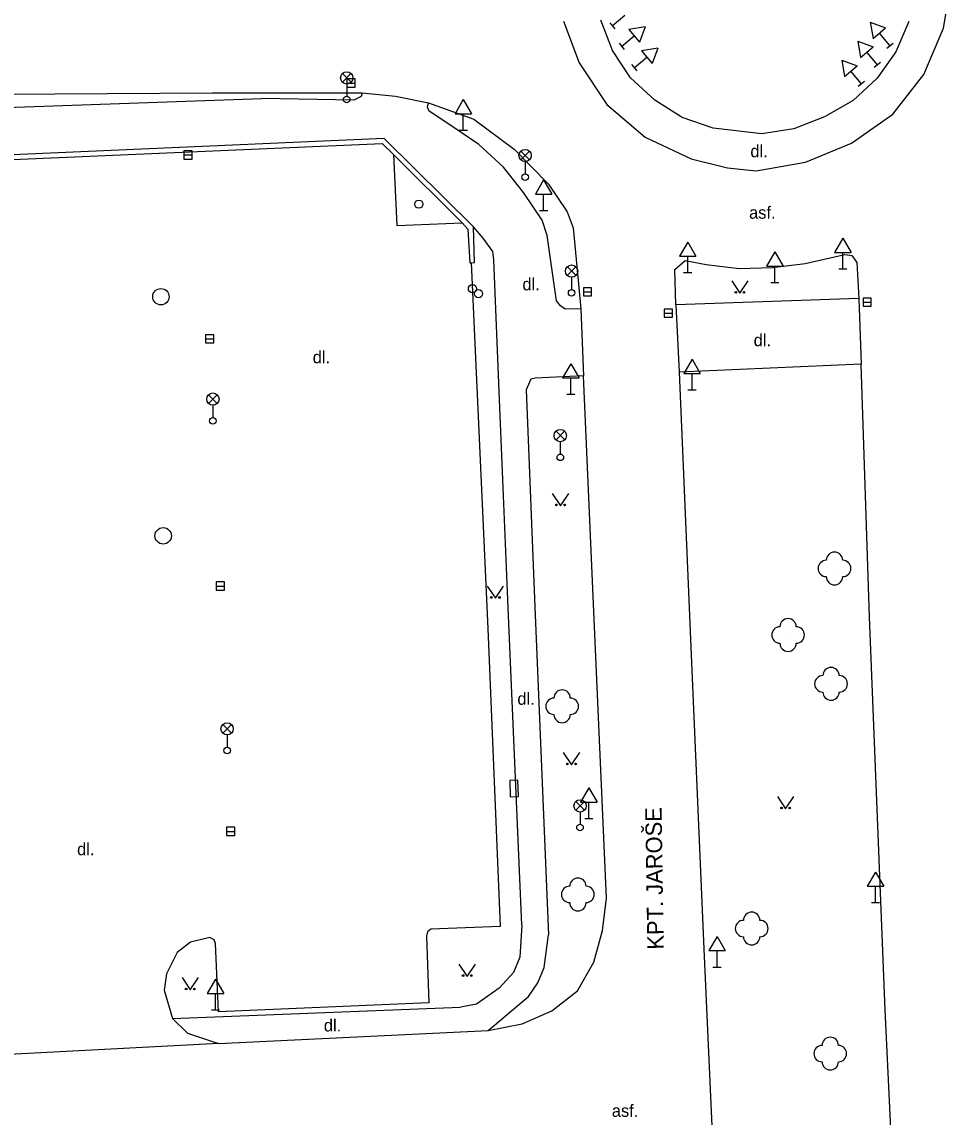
# Model space of a CAD drawing. Extents: x -737812 to -729375, y -1123000 to -1115500.
# Drawn here: x -736401.9 to -736345.8, y -1118917.3 to -1118850.5 of the extents above; entities that cross this region are included whole.
import ezdxf

# ---------------------------------------------------------------- set-up
doc = ezdxf.new("R2010")
doc.units = 0
for name, color, linetype in [('Doplněk polohopisu', 7, 'Continuous'), ('Doplňkové značky', 7, 'Continuous'), ('Hranice - ploty_ zdi', 7, 'Continuous'), ('Komunikace', 7, 'Continuous'), ('Názvy ulic_ silnic_ žel_', 7, 'Continuous'), ('Pomocné popisy', 7, 'Continuous'), ('Povr_ zn_ inž_ sítí - el_', 7, 'Continuous'), ('Povr_ zn_ inž_ sítí - kan_', 7, 'Continuous'), ('Povr_ zn_ inž_ sítí - vod_', 7, 'Continuous'), ('Zeleň', 7, 'Continuous'), ('Značky druhů pozemků', 7, 'Continuous')]:
    doc.layers.add(name, color=color, linetype=linetype)

msp = doc.modelspace()

# ---------------------------------------------------------------- linework, layer by layer
at = {"layer": 'Doplněk polohopisu'}
for points in [[(-736453.53, -1118857.19), (-736433.11, -1118856.6), (-736413.31, -1118856.09), (-736387.26, -1118855.18)], [(-736381.14, -1118854.83), (-736381.2, -1118855.06), (-736381.66, -1118855.27), (-736387.26, -1118855.18)], [(-736367.8, -1118868), (-736368.76, -1118868.02), (-736369.05, -1118867.83), (-736369.3, -1118867.52), (-736369.87, -1118863.53), (-736370.17, -1118862.59), (-736371.3, -1118860.9), (-736372.53, -1118859.36), (-736374.02, -1118857.98), (-736375.67, -1118856.86), (-736377.05, -1118855.95), (-736377.16, -1118855.7), (-736377.1, -1118855.44)], [(-736371.4, -1118905.59), (-736372.21, -1118887.2), (-736372.78, -1118873.05), (-736373.12, -1118865.01), (-736373.17, -1118864.51), (-736373.76, -1118863.69), (-736374.36, -1118863)], [(-736350.85, -1118867.38), (-736362.01, -1118867.76)], [(-736350.72, -1118871.39), (-736361.81, -1118871.88)], [(-736367.64, -1118872.1), (-736370.6, -1118872.23), (-736370.85, -1118872.29), (-736371.14, -1118872.95), (-736370.6, -1118886.7), (-736369.78, -1118906.21)], [(-736371.4, -1118905.59), (-736371.53, -1118907.57), (-736371.91, -1118908.5), (-736372.78, -1118909.46), (-736374.17, -1118910.44), (-736375.15, -1118910.62)], [(-736373.47, -1118912.04), (-736371.01, -1118909.97), (-736370.44, -1118909.13), (-736370.05, -1118908.2), (-736369.78, -1118906.21)], [(-736392.71, -1118911.31), (-736375.15, -1118910.62)]]:
    msp.add_lwpolyline(points, dxfattribs=at)
at = {"layer": 'Doplňkové značky'}
for p, q in [((-736366.051, -1118850.548), (-736365.729, -1118850.932)), ((-736365.89, -1118850.74), (-736365.124, -1118850.097)), ((-736350.159, -1118850.521), (-736349.986, -1118851.505)), ((-736350.159, -1118850.521), (-736349.22, -1118850.863)), ((-736363.891, -1118850.801), (-736364.875, -1118850.974)), ((-736364.875, -1118850.974), (-736364.233, -1118851.74)), ((-736363.891, -1118850.801), (-736364.233, -1118851.74)), ((-736349.986, -1118851.505), (-736349.22, -1118850.863)), ((-736348.96, -1118851.95), (-736349.603, -1118851.184)), ((-736365.481, -1118851.808), (-736365.159, -1118852.192)), ((-736365.32, -1118852), (-736364.554, -1118851.357)), ((-736350.919, -1118851.681), (-736350.746, -1118852.665)), ((-736350.919, -1118851.681), (-736349.98, -1118852.023)), ((-736349.152, -1118852.111), (-736348.768, -1118851.789)), ((-736364.55, -1118853.3), (-736363.784, -1118852.657)), ((-736363.121, -1118852.101), (-736364.105, -1118852.274)), ((-736364.105, -1118852.274), (-736363.463, -1118853.04)), ((-736363.121, -1118852.101), (-736363.463, -1118853.04)), ((-736350.746, -1118852.665), (-736349.98, -1118852.023)), ((-736349.72, -1118853.11), (-736350.363, -1118852.344)), ((-736364.711, -1118853.108), (-736364.389, -1118853.492)), ((-736351.899, -1118852.841), (-736351.726, -1118853.825)), ((-736351.899, -1118852.841), (-736350.96, -1118853.183)), ((-736351.726, -1118853.825), (-736350.96, -1118853.183)), ((-736349.912, -1118853.271), (-736349.528, -1118852.949)), ((-736350.7, -1118854.27), (-736351.343, -1118853.504)), ((-736350.892, -1118854.431), (-736350.508, -1118854.109)), ((-736374.98, -1118855.244), (-736375.48, -1118856.11)), ((-736374.98, -1118855.244), (-736374.48, -1118856.11)), ((-736375.48, -1118856.11), (-736374.48, -1118856.11)), ((-736374.98, -1118857.11), (-736374.98, -1118856.11)), ((-736375.23, -1118857.11), (-736374.73, -1118857.11)), ((-736370.08, -1118860.144), (-736370.58, -1118861.01)), ((-736370.08, -1118860.144), (-736369.58, -1118861.01)), ((-736370.58, -1118861.01), (-736369.58, -1118861.01)), ((-736370.08, -1118862.01), (-736370.08, -1118861.01)), ((-736370.33, -1118862.01), (-736369.83, -1118862.01)), ((-736361.29, -1118863.934), (-736361.79, -1118864.8)), ((-736361.29, -1118863.934), (-736360.79, -1118864.8)), ((-736351.83, -1118863.704), (-736352.33, -1118864.57)), ((-736351.83, -1118863.704), (-736351.33, -1118864.57)), ((-736355.98, -1118864.534), (-736356.48, -1118865.4)), ((-736355.98, -1118864.534), (-736355.48, -1118865.4)), ((-736352.33, -1118864.57), (-736351.33, -1118864.57)), ((-736351.83, -1118865.57), (-736351.83, -1118864.57)), ((-736361.79, -1118864.8), (-736360.79, -1118864.8)), ((-736361.29, -1118865.8), (-736361.29, -1118864.8)), ((-736361.54, -1118865.8), (-736361.04, -1118865.8)), ((-736356.48, -1118865.4), (-736355.48, -1118865.4)), ((-736355.98, -1118866.4), (-736355.98, -1118865.4)), ((-736352.08, -1118865.57), (-736351.58, -1118865.57)), ((-736356.23, -1118866.4), (-736355.73, -1118866.4)), ((-736368.42, -1118871.354), (-736368.92, -1118872.22)), ((-736368.42, -1118871.354), (-736367.92, -1118872.22)), ((-736361.03, -1118871.084), (-736361.53, -1118871.95)), ((-736361.03, -1118871.084), (-736360.53, -1118871.95)), ((-736361.53, -1118871.95), (-736360.53, -1118871.95)), ((-736361.03, -1118872.95), (-736361.03, -1118871.95)), ((-736368.92, -1118872.22), (-736367.92, -1118872.22)), ((-736368.42, -1118873.22), (-736368.42, -1118872.22)), ((-736368.67, -1118873.22), (-736368.17, -1118873.22)), ((-736361.28, -1118872.95), (-736360.78, -1118872.95)), ((-736367.32, -1118897.244), (-736367.82, -1118898.11)), ((-736367.32, -1118897.244), (-736366.82, -1118898.11)), ((-736367.82, -1118898.11), (-736366.82, -1118898.11)), ((-736367.32, -1118899.11), (-736367.32, -1118898.11)), ((-736367.57, -1118899.11), (-736367.07, -1118899.11)), ((-736349.84, -1118902.374), (-736350.34, -1118903.24)), ((-736349.84, -1118902.374), (-736349.34, -1118903.24)), ((-736350.34, -1118903.24), (-736349.34, -1118903.24)), ((-736349.84, -1118904.24), (-736349.84, -1118903.24)), ((-736350.09, -1118904.24), (-736349.59, -1118904.24)), ((-736359.5, -1118906.304), (-736360, -1118907.17)), ((-736359.5, -1118906.304), (-736359, -1118907.17)), ((-736360, -1118907.17), (-736359, -1118907.17)), ((-736359.5, -1118908.17), (-736359.5, -1118907.17)), ((-736359.75, -1118908.17), (-736359.25, -1118908.17)), ((-736390.09, -1118908.914), (-736390.59, -1118909.78)), ((-736390.09, -1118908.914), (-736389.59, -1118909.78)), ((-736390.59, -1118909.78), (-736389.59, -1118909.78)), ((-736390.09, -1118910.78), (-736390.09, -1118909.78)), ((-736390.34, -1118910.78), (-736389.84, -1118910.78))]:
    msp.add_line(p, q, dxfattribs=at)
at = {"layer": 'Hranice - ploty_ zdi'}
for p, q in [((-736379.8, -1118857.61), (-736409.77, -1118858.93)), ((-736409.51, -1118859.21), (-736379.93, -1118857.91)), ((-736379.93, -1118857.91), (-736379.24, -1118858.59)), ((-736374.36, -1118863), (-736379.8, -1118857.61)), ((-736379.24, -1118858.59), (-736375.05, -1118862.77)), ((-736375.05, -1118862.77), (-736374.71, -1118863.14)), ((-736374.71, -1118863.14), (-736374.58, -1118865.2)), ((-736374.3, -1118865.18), (-736374.36, -1118863)), ((-736374.58, -1118865.2), (-736374.5, -1118865.2)), ((-736374.5, -1118865.2), (-736374.3, -1118865.18))]:
    msp.add_line(p, q, dxfattribs=at)
at = {"layer": 'Komunikace'}
for points in [[(-736361.08, -1118858.86), (-736358.87, -1118859.41), (-736357.12, -1118859.58), (-736354.1, -1118859.06), (-736351.3, -1118857.89), (-736348.79, -1118856.12), (-736346.89, -1118853.7), (-736345.7, -1118850.88), (-736345.19, -1118847.83)], [(-736368.86, -1118850.46), (-736367.92, -1118852.99), (-736366.23, -1118855.54), (-736363.88, -1118857.54), (-736361.08, -1118858.86)], [(-736359.74, -1118856.98), (-736361.63, -1118856.33), (-736363.3, -1118855.27), (-736364.79, -1118853.92), (-736365.87, -1118852.24), (-736366.59, -1118850.39)], [(-736347.8, -1118850.48), (-736348.6, -1118852.32), (-736349.73, -1118853.94), (-736351.21, -1118855.3), (-736352.94, -1118856.29), (-736354.81, -1118857.03), (-736356.78, -1118857.34), (-736359.74, -1118856.98)], [(-736428.76, -1118855.15), (-736406.31, -1118854.93), (-736390.28, -1118854.83), (-736381.14, -1118854.83)], [(-736381.14, -1118854.83), (-736379.11, -1118855.04), (-736377.1, -1118855.44)], [(-736377.1, -1118855.44), (-736374.33, -1118856.44), (-736371.88, -1118858.26), (-736369.78, -1118860.4), (-736368.64, -1118862.08), (-736368.28, -1118863.06), (-736367.8, -1118868)], [(-736379.24, -1118858.59), (-736379.03, -1118862.92), (-736375.05, -1118862.77)], [(-736362.01, -1118867.76), (-736362.08, -1118865.6), (-736361.45, -1118865.05), (-736360.16, -1118865.3), (-736358.15, -1118865.54), (-736356.12, -1118865.48), (-736354.13, -1118865.24), (-736351.7, -1118864.69), (-736351.29, -1118864.76), (-736350.97, -1118865.19), (-736350.85, -1118867.38)], [(-736374.5, -1118865.2), (-736373.48, -1118887.51), (-736372.73, -1118905.7), (-736376.95, -1118905.85), (-736377.16, -1118906.02), (-736377.22, -1118906.29), (-736377.07, -1118910.35), (-736389.91, -1118910.91), (-736390.09, -1118906.73), (-736390.17, -1118906.51), (-736390.43, -1118906.36), (-736391.61, -1118906.65), (-736392.43, -1118907.29), (-736393.07, -1118908.59), (-736393.22, -1118909.59), (-736392.71, -1118911.31)], [(-736350.85, -1118867.38), (-736350.72, -1118871.39)], [(-736367.8, -1118868), (-736367.64, -1118872.1)], [(-736362.01, -1118867.76), (-736361.81, -1118871.88)], [(-736348.71, -1118922.32), (-736349.26, -1118910.79), (-736350.2, -1118886.8), (-736350.72, -1118871.39)], [(-736361.81, -1118871.88), (-736361.04, -1118890.08), (-736360.3, -1118907.05), (-736359.67, -1118921.04)], [(-736373.47, -1118912.04), (-736371.39, -1118911.64), (-736369.57, -1118910.85), (-736368.01, -1118909.62), (-736367.02, -1118907.88), (-736366.49, -1118905.93), (-736366.24, -1118903.96), (-736366.99, -1118886.94), (-736367.64, -1118872.1)], [(-736392.71, -1118911.31), (-736391.79, -1118912.2), (-736389.9, -1118912.84), (-736373.47, -1118912.04)], [(-736389.9, -1118912.84), (-736405, -1118913.62)]]:
    msp.add_lwpolyline(points, dxfattribs=at)
at = {"layer": 'Povr_ zn_ inž_ sítí - el_'}
for p, q in [((-736382.354, -1118854.178), (-736381.826, -1118853.65)), ((-736381.818, -1118854.175), (-736382.346, -1118853.646)), ((-736382.09, -1118854.29), (-736382.09, -1118855.04)), ((-736371.474, -1118858.918), (-736370.946, -1118858.39)), ((-736370.938, -1118858.915), (-736371.466, -1118858.386)), ((-736371.21, -1118859.03), (-736371.21, -1118859.78)), ((-736368.634, -1118865.968), (-736368.106, -1118865.44)), ((-736368.098, -1118865.965), (-736368.626, -1118865.436)), ((-736368.37, -1118866.08), (-736368.37, -1118866.83)), ((-736390.514, -1118873.778), (-736389.986, -1118873.25)), ((-736389.978, -1118873.775), (-736390.506, -1118873.246)), ((-736390.25, -1118873.89), (-736390.25, -1118874.64)), ((-736369.324, -1118876.008), (-736368.796, -1118875.48)), ((-736368.788, -1118876.005), (-736369.316, -1118875.476)), ((-736369.06, -1118876.12), (-736369.06, -1118876.87)), ((-736389.644, -1118893.898), (-736389.116, -1118893.37)), ((-736389.108, -1118893.895), (-736389.636, -1118893.366)), ((-736389.38, -1118894.01), (-736389.38, -1118894.76)), ((-736368.124, -1118898.598), (-736367.596, -1118898.07)), ((-736367.588, -1118898.595), (-736368.116, -1118898.066)), ((-736367.86, -1118898.71), (-736367.86, -1118899.46))]:
    msp.add_line(p, q, dxfattribs=at)
msp.add_lwpolyline([(-736371.617, -1118897.773), (-736371.643, -1118896.774), (-736372.143, -1118896.787), (-736372.117, -1118897.786)], close=True, dxfattribs=at)
for centre, radius in [((-736382.09, -1118853.915), 0.375), ((-736382.09, -1118855.24), 0.2), ((-736371.21, -1118858.655), 0.375), ((-736371.21, -1118859.98), 0.2), ((-736377.69, -1118861.62), 0.25), ((-736368.37, -1118865.705), 0.375), ((-736368.37, -1118867.03), 0.2), ((-736390.25, -1118873.515), 0.375), ((-736390.25, -1118874.84), 0.2), ((-736369.06, -1118875.745), 0.375), ((-736369.06, -1118877.07), 0.2), ((-736389.38, -1118893.635), 0.375), ((-736389.38, -1118894.96), 0.2), ((-736367.86, -1118898.335), 0.375), ((-736367.86, -1118899.66), 0.2)]:
    msp.add_circle(centre, radius, dxfattribs=at)
at = {"layer": 'Povr_ zn_ inž_ sítí - kan_'}
for p, q in [((-736382.08, -1118854.23), (-736381.58, -1118854.23)), ((-736392.02, -1118858.62), (-736391.52, -1118858.62)), ((-736367.65, -1118866.97), (-736367.15, -1118866.97)), ((-736350.6, -1118867.6), (-736350.1, -1118867.6)), ((-736362.72, -1118868.27), (-736362.22, -1118868.27)), ((-736390.7, -1118869.84), (-736390.2, -1118869.84)), ((-736390.05, -1118884.92), (-736389.55, -1118884.92)), ((-736389.41, -1118899.89), (-736388.91, -1118899.89))]:
    msp.add_line(p, q, dxfattribs=at)
for points in [[(-736382.08, -1118854.481), (-736381.58, -1118854.481), (-736381.58, -1118853.98), (-736382.08, -1118853.98)], [(-736392.02, -1118858.871), (-736391.52, -1118858.871), (-736391.52, -1118858.37), (-736392.02, -1118858.37)], [(-736367.65, -1118867.221), (-736367.15, -1118867.221), (-736367.15, -1118866.72), (-736367.65, -1118866.72)], [(-736350.6, -1118867.851), (-736350.1, -1118867.851), (-736350.1, -1118867.35), (-736350.6, -1118867.35)], [(-736362.72, -1118868.521), (-736362.22, -1118868.521), (-736362.22, -1118868.02), (-736362.72, -1118868.02)], [(-736390.7, -1118870.091), (-736390.2, -1118870.091), (-736390.2, -1118869.59), (-736390.7, -1118869.59)], [(-736390.05, -1118885.171), (-736389.55, -1118885.171), (-736389.55, -1118884.67), (-736390.05, -1118884.67)], [(-736389.41, -1118900.141), (-736388.91, -1118900.141), (-736388.91, -1118899.64), (-736389.41, -1118899.64)]]:
    msp.add_lwpolyline(points, close=True, dxfattribs=at)
for centre in [(-736393.42, -1118867.27), (-736393.28, -1118881.86)]:
    msp.add_circle(centre, 0.5, dxfattribs=at)
at = {"layer": 'Povr_ zn_ inž_ sítí - vod_'}
for centre in [(-736374.42, -1118866.78), (-736374.05, -1118867.08)]:
    msp.add_circle(centre, 0.25, dxfattribs=at)
at = {"layer": 'Zeleň'}
for centre in [(-736352.34, -1118883.85), (-736355.17, -1118887.91), (-736352.55, -1118890.89), (-736368.95, -1118892.26), (-736367.99, -1118903.74), (-736357.39, -1118905.82), (-736352.6, -1118913.45)]:
    msp.add_circle(centre, 0.0005, dxfattribs=at)
for centre, start, end in [((-736352.84, -1118883.85), 89.99999, 269.99999), ((-736352.34, -1118883.35), 360, 179.99999), ((-736351.84, -1118883.85), 270, 89.99999), ((-736352.34, -1118884.35), 179.99999, 359.99999), ((-736355.67, -1118887.91), 89.99999, 269.99999), ((-736355.17, -1118887.41), 360, 179.99999), ((-736354.67, -1118887.91), 270, 89.99999), ((-736355.17, -1118888.41), 179.99999, 359.99999), ((-736352.55, -1118890.39), 360, 179.99999), ((-736353.05, -1118890.89), 89.99999, 269.99999), ((-736352.05, -1118890.89), 270, 89.99999), ((-736368.95, -1118891.76), 0, 179.99999), ((-736352.55, -1118891.39), 179.99999, 359.99999), ((-736369.45, -1118892.26), 89.99999, 269.99999), ((-736368.45, -1118892.26), 270, 89.99999), ((-736368.95, -1118892.76), 179.99999, 359.99999), ((-736367.99, -1118903.24), 0, 179.99999), ((-736368.49, -1118903.74), 89.99999, 269.99999), ((-736367.49, -1118903.74), 270, 89.99999), ((-736367.99, -1118904.24), 179.99999, 359.99999), ((-736357.89, -1118905.82), 89.99999, 269.99999), ((-736357.39, -1118905.32), 360, 179.99999), ((-736356.89, -1118905.82), 270, 89.99999), ((-736357.39, -1118906.32), 179.99999, 359.99999), ((-736352.6, -1118912.95), 360, 179.99999), ((-736353.1, -1118913.45), 89.99999, 269.99999), ((-736352.1, -1118913.45), 270, 89.99999), ((-736352.6, -1118913.95), 179.99999, 359.99999)]:
    msp.add_arc(centre, 0.5, start, end, dxfattribs=at)
at = {"layer": 'Značky druhů pozemků'}
for points in [[(-736358.61, -1118866.3), (-736358.11, -1118867.05), (-736357.61, -1118866.3)], [(-736369.55, -1118879.27), (-736369.05, -1118880.02), (-736368.55, -1118879.27)], [(-736373.52, -1118884.92), (-736373.02, -1118885.67), (-736372.52, -1118884.92)], [(-736368.88, -1118895.08), (-736368.38, -1118895.83), (-736367.88, -1118895.08)], [(-736355.82, -1118897.77), (-736355.32, -1118898.52), (-736354.82, -1118897.77)], [(-736375.24, -1118907.99), (-736374.74, -1118908.74), (-736374.24, -1118907.99)], [(-736392.13, -1118908.81), (-736391.63, -1118909.56), (-736391.13, -1118908.81)]]:
    msp.add_lwpolyline(points, dxfattribs=at)
for centre in [(-736358.36, -1118867), (-736357.86, -1118867), (-736369.3, -1118879.97), (-736368.8, -1118879.97), (-736373.27, -1118885.62), (-736372.77, -1118885.62), (-736368.63, -1118895.78), (-736368.13, -1118895.78), (-736355.57, -1118898.47), (-736355.07, -1118898.47), (-736374.99, -1118908.69), (-736374.49, -1118908.69), (-736391.88, -1118909.51), (-736391.38, -1118909.51)]:
    msp.add_circle(centre, 0.05, dxfattribs=at)

# ---------------------------------------------------------------- texts
at = {"layer": 'Názvy ulic_ silnic_ žel_'}
msp.add_text('KPT. JAROŠE', height=1, rotation=90.89546, dxfattribs=at).set_placement((-736362.75, -1118907.1))
at = {"layer": 'Pomocné popisy'}
for s, p in [('dl.', (-736357.47, -1118858.76)), ('asf.', (-736357.55, -1118862.51)), ('dl.', (-736371.37, -1118866.88)), ('dl.', (-736357.27, -1118870.29)), ('dl.', (-736384.16, -1118871.33)), ('dl.', (-736371.68, -1118892.17)), ('dl.', (-736398.53, -1118901.35)), ('dl.', (-736383.48, -1118912.1)), ('asf.', (-736365.92, -1118917.31))]:
    msp.add_text(s, height=0.75, dxfattribs=at).set_placement(p)

doc.saveas('drawing.dxf')
